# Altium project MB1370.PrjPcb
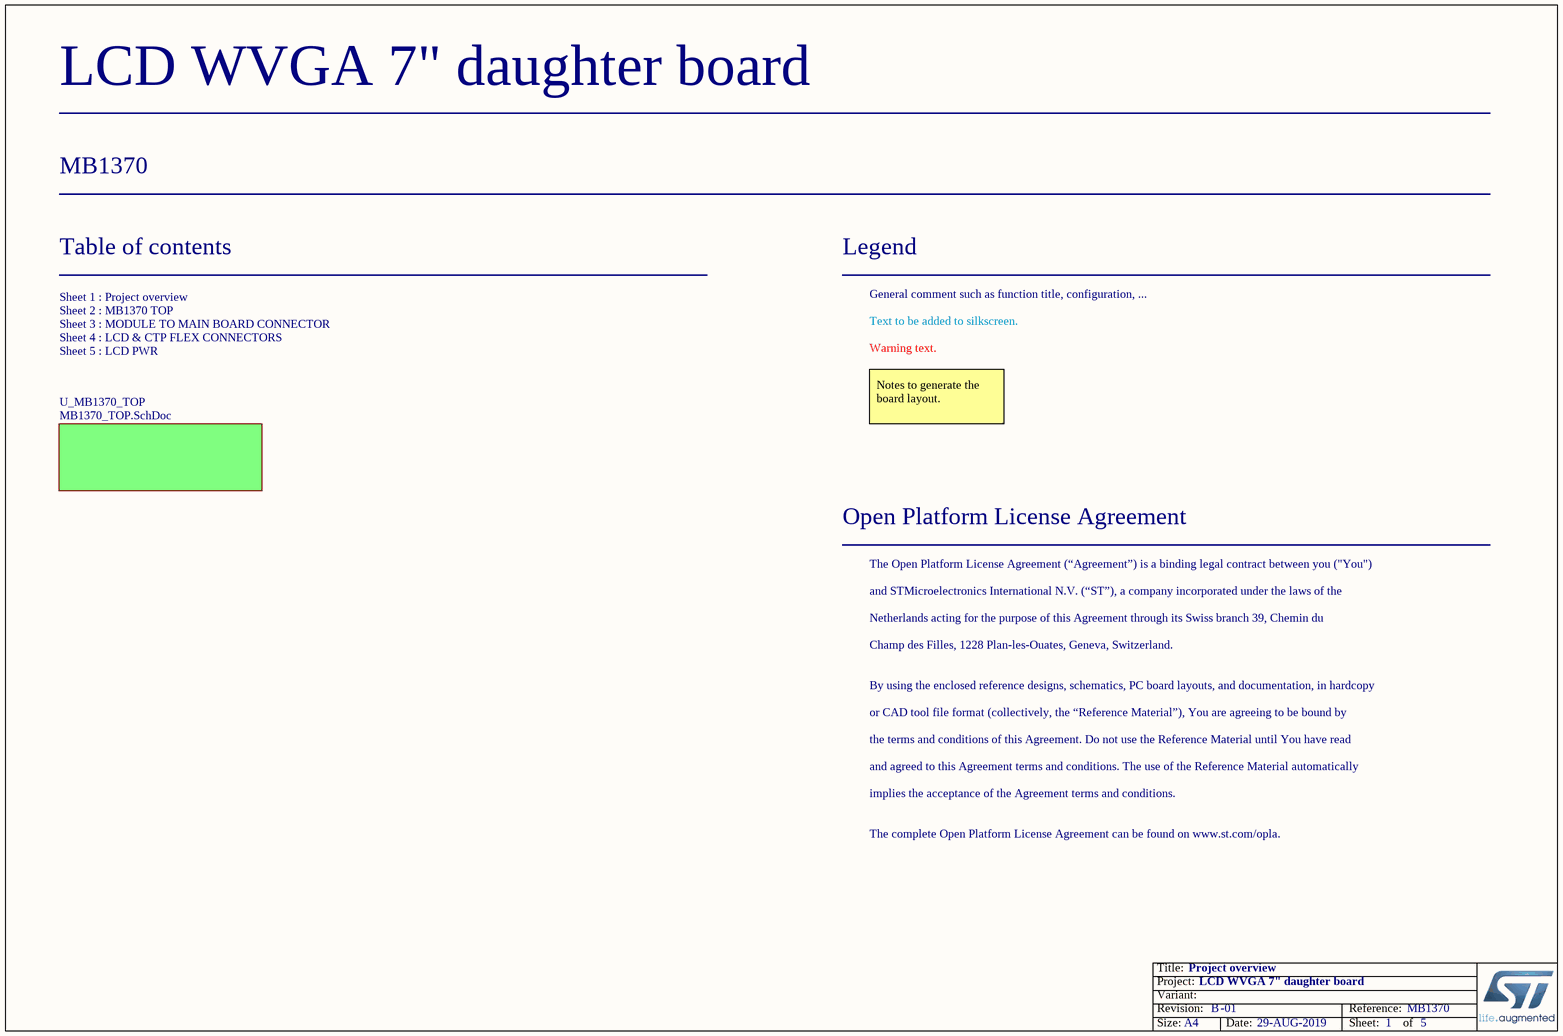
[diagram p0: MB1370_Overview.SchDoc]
Board_Assembly_Revision: 01; Board_Document_Date: 29-AUG-2019; Board_Name: LCD WVGA 7" daughter board; Board_PCB_Revision: B; Board_Reference: MB1370
5 sheets, 77 parts. Net scope: flat (ports and power ports of the same name join across sheets).
Board file: MB1370.PcbDoc
Sheets:
  MB1370_Overview.SchDoc
    U_MB1370_TOP = MB1370_TOP.SchDoc
      U_MODULE_TO_MAIN_BOARD_CONNECTOR = MODULE_TO_MAIN_BOARD_CONNECTOR.SchDoc
      U_LCD_CTP_FLEX_CONNECTORS = LCD_CTP_FLEX_CONNECTORS.SchDoc
      U_LCD_PWR = LCD_PWR.SchDoc

## Sheet MB1370_Overview.SchDoc: Project overview
size A4; Date: Not used; ApprovedBy: Not used; CheckedBy: Not used; Author: Not used; CompanyName: STMicroelectronics; DrawnBy: Not used; Engineer: Not used; Organization: Not used; Address1: Not used; Address2: Not used; Address3: Not used; Address4: Not used; DocumentNumber: Not used; Revision: Not used; SheetNumber: 1; SheetTotal: 5

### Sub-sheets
U_MB1370_TOP = MB1370_TOP.SchDoc: no entries

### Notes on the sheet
- Table of contents
- Legend
- General comment such as function title, configuration, ...
- Text to be added to silkscreen.
- Warning text.
- Sheet 1 : Project overview
  Sheet 2 : MB1370 TOP
  Sheet 3 : MODULE TO MAIN BOARD CONNECTOR
  Sheet 4 : LCD & CTP FLEX CONNECTORS
  Sheet 5 : LCD PWR
- Notes to generate the board layout.
- Open Platform License Agreement
- The Open Platform License Agreement (“Agreement”) is a binding legal contract between you ("You")
- and STMicroelectronics International N.V. (“ST”), a company incorporated under the laws of the
- Netherlands acting for the purpose of this Agreement through its Swiss branch 39, Chemin du
- Champ des Filles, 1228 Plan-les-Ouates, Geneva, Switzerland.
- By using the enclosed reference designs, schematics, PC board layouts, and documentation, in hardcopy
- or CAD tool file format (collectively, the “Reference Material”), You are agreeing to be bound by
- the terms and conditions of this Agreement. Do not use the Reference Material until You have read
- and agreed to this Agreement terms and conditions. The use of the Reference Material automatically
- implies the acceptance of the Agreement terms and conditions.
- The complete Open Platform License Agreement can be found on www.st.com/opla.

## Sheet MB1370_TOP.SchDoc: MB1370 TOP
size A4; Date: Not used; ApprovedBy: Not used; CheckedBy: Not used; Author: Not used; CompanyName: STMicroelectronics; DrawnBy: Not used; Engineer: Not used; Organization: Not used; Address1: Not used; Address2: Not used; Address3: Not used; Address4: Not used; DocumentNumber: Not used; Revision: Not used; SheetNumber: 2; SheetTotal: 5
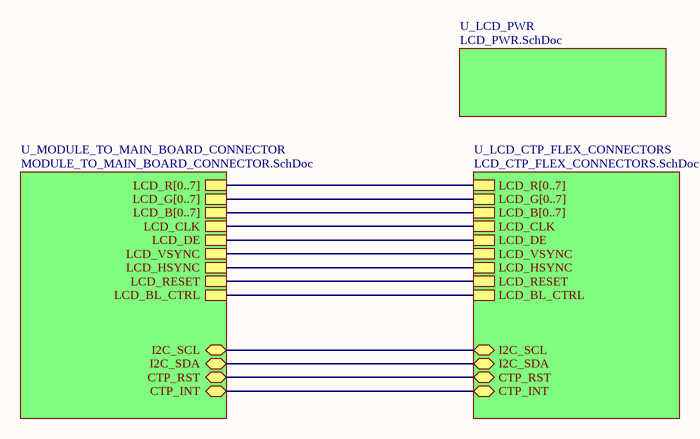
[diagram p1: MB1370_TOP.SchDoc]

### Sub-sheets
U_LCD_CTP_FLEX_CONNECTORS = LCD_CTP_FLEX_CONNECTORS.SchDoc: LCD_R[0..7], LCD_B[0..7], LCD_G[0..7], LCD_RESET, LCD_BL_CTRL, LCD_HSYNC, LCD_VSYNC, LCD_CLK, LCD_DE, I2C_SDA, I2C_SCL, CTP_RST, CTP_INT
U_LCD_PWR = LCD_PWR.SchDoc: no entries
U_MODULE_TO_MAIN_BOARD_CONNECTOR = MODULE_TO_MAIN_BOARD_CONNECTOR.SchDoc: LCD_R[0..7], LCD_B[0..7], LCD_G[0..7], LCD_HSYNC, LCD_VSYNC, LCD_CLK, LCD_DE, LCD_BL_CTRL, LCD_RESET, I2C_SCL, I2C_SDA, CTP_RST, CTP_INT

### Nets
(unnamed): sheet U_MODULE_TO_MAIN_BOARD_CONNECTOR/LCD_HSYNC, sheet U_LCD_CTP_FLEX_CONNECTORS/LCD_HSYNC
(unnamed): sheet U_MODULE_TO_MAIN_BOARD_CONNECTOR/LCD_VSYNC, sheet U_LCD_CTP_FLEX_CONNECTORS/LCD_VSYNC  [a separate net that carries the same name]
(unnamed): sheet U_MODULE_TO_MAIN_BOARD_CONNECTOR/LCD_CLK, sheet U_LCD_CTP_FLEX_CONNECTORS/LCD_CLK  [a separate net that carries the same name]
(unnamed): sheet U_MODULE_TO_MAIN_BOARD_CONNECTOR/LCD_DE, sheet U_LCD_CTP_FLEX_CONNECTORS/LCD_DE  [a separate net that carries the same name]
(unnamed): sheet U_MODULE_TO_MAIN_BOARD_CONNECTOR/LCD_BL_CTRL, sheet U_LCD_CTP_FLEX_CONNECTORS/LCD_BL_CTRL  [a separate net that carries the same name]
(unnamed): sheet U_MODULE_TO_MAIN_BOARD_CONNECTOR/LCD_RESET, sheet U_LCD_CTP_FLEX_CONNECTORS/LCD_RESET  [a separate net that carries the same name]
(unnamed): sheet U_MODULE_TO_MAIN_BOARD_CONNECTOR/I2C_SCL, sheet U_LCD_CTP_FLEX_CONNECTORS/I2C_SCL  [a separate net that carries the same name]
(unnamed): sheet U_MODULE_TO_MAIN_BOARD_CONNECTOR/I2C_SDA, sheet U_LCD_CTP_FLEX_CONNECTORS/I2C_SDA  [a separate net that carries the same name]
(unnamed): sheet U_MODULE_TO_MAIN_BOARD_CONNECTOR/CTP_RST, sheet U_LCD_CTP_FLEX_CONNECTORS/CTP_RST  [a separate net that carries the same name]
(unnamed): sheet U_MODULE_TO_MAIN_BOARD_CONNECTOR/CTP_INT, sheet U_LCD_CTP_FLEX_CONNECTORS/CTP_INT  [a separate net that carries the same name]

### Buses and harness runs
bus sheet U_LCD_CTP_FLEX_CONNECTORS/LCD_B[0..7] = sheet U_MODULE_TO_MAIN_BOARD_CONNECTOR/LCD_B[0..7]
bus sheet U_LCD_CTP_FLEX_CONNECTORS/LCD_G[0..7] = sheet U_MODULE_TO_MAIN_BOARD_CONNECTOR/LCD_G[0..7]
bus sheet U_LCD_CTP_FLEX_CONNECTORS/LCD_R[0..7] = sheet U_MODULE_TO_MAIN_BOARD_CONNECTOR/LCD_R[0..7]

## Sheet MODULE_TO_MAIN_BOARD_CONNECTOR.SchDoc: MODULE TO MAIN BOARD CONNECTOR
size A4; Date: Not used; ApprovedBy: Not used; CheckedBy: Not used; Author: Not used; CompanyName: STMicroelectronics; DrawnBy: Not used; Engineer: Not used; Organization: Not used; Address1: Not used; Address2: Not used; Address3: Not used; Address4: Not used; DocumentNumber: Not used; Revision: Not used; SheetNumber: 3; SheetTotal: 5
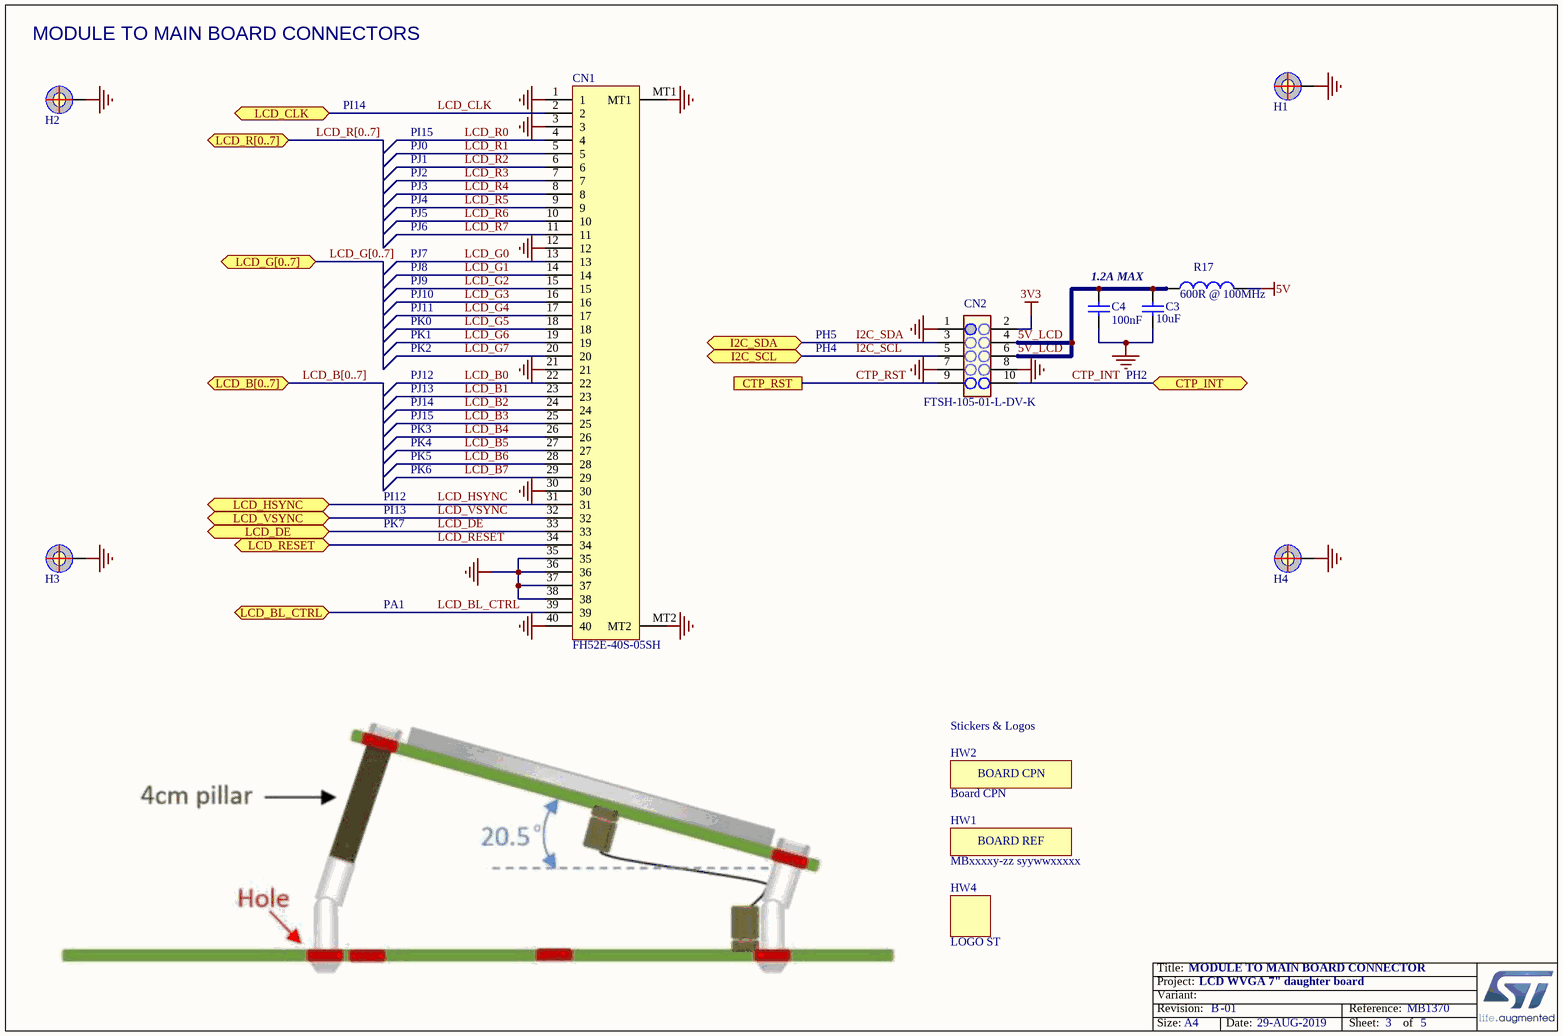
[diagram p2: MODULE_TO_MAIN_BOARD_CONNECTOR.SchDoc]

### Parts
C3  value 10uF  [C0805]  (hidden comment: Capacitor)
C4  value 100nF  [C0402]  (hidden comment: Capacitor)
CN1  value FH52E-40S-05SH  [CON_HRS_FH52E-40S-05SH]  (hidden comment: FH52E-40S-0.5SH)
CN2  value FTSH-105-01-L-DV-K  [CON_SAMTEC_FTSH-105-01-L-DV-K]  (hidden comment: Header 5x2 Generic)
H1  POSITION HOLE  [PTH_M1261-3005-N_3P5X6_M3_H14]  (value not drawn)  (no BOM)
H2  POSITION HOLE  [PTH_M1261-3005-N_3P5X6_M3_H14]  (value not drawn)  (no BOM)
H3  POSITION HOLE  [PTH_M1261-3005-N_3P5X6_M3_H14]  (value not drawn)  (no BOM)
H4  POSITION HOLE  [PTH_M1261-3005-N_3P5X6_M3_H14]  (value not drawn)  (no BOM)
HW1  value MBxxxxy-zz syywwxxxxx  [STICKER_25X9]  (hidden comment: STICKER_BOARD_REF)  (no BOM)
HW2  value Board CPN  [STICKER_25X9]  (hidden comment: STICKER_BOARD_CPN)  (no BOM)
HW4  value LOGO ST  [LOGO_ST]  (hidden comment: Logo)  (no BOM)
R17  value 600R @ 100MHz  [IND_0603_H0P8]  (hidden comment: Inductor)

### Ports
CTP_INT, CTP_RST, I2C_SCL, I2C_SDA, LCD_B[0..7], LCD_BL_CTRL, LCD_CLK, LCD_DE, LCD_G[0..7], LCD_HSYNC, LCD_R[0..7], LCD_RESET, LCD_VSYNC

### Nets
3V3: CN2.2
5V: R17.2
GND: C3.1 C4.2 CN1.1 CN1.3 CN1.12 CN1.21 CN1.30 CN1.35 CN1.36 CN1.37 CN1.38 CN1.40 CN1.MT1 CN1.MT2 CN2.1 CN2.7 CN2.8 H1.1 H2.1 H3.1 H4.1
5V_LCD: C3.2 C4.1 CN2.4 CN2.6 R17.1
CTP_INT: CN2.10 ; port CTP_INT
CTP_RST: CN2.9 ; port CTP_RST
I2C_SCL: CN2.5 ; port I2C_SCL
I2C_SDA: CN2.3 ; port I2C_SDA
LCD_B0: CN1.22
LCD_B1: CN1.23
LCD_B2: CN1.24
LCD_B3: CN1.25
LCD_B4: CN1.26
LCD_B5: CN1.27
LCD_B6: CN1.28
LCD_B7: CN1.29
LCD_BL_CTRL: CN1.39 ; port LCD_BL_CTRL
LCD_CLK: CN1.2 ; port LCD_CLK
LCD_DE: CN1.33 ; port LCD_DE
LCD_G0: CN1.13
LCD_G1: CN1.14
LCD_G2: CN1.15
LCD_G3: CN1.16
LCD_G4: CN1.17
LCD_G5: CN1.18
LCD_G6: CN1.19
LCD_G7: CN1.20
LCD_HSYNC: CN1.31 ; port LCD_HSYNC
LCD_R0: CN1.4
LCD_R1: CN1.5
LCD_R2: CN1.6
LCD_R3: CN1.7
LCD_R4: CN1.8
LCD_R5: CN1.9
LCD_R6: CN1.10
LCD_R7: CN1.11
LCD_RESET: CN1.34 ; port LCD_RESET
LCD_VSYNC: CN1.32 ; port LCD_VSYNC

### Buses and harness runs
bus LCD_B[0..7] = port LCD_B[0..7]
bus LCD_G[0..7] = port LCD_G[0..7]
bus LCD_R[0..7] = port LCD_R[0..7]

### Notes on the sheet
- MODULE TO MAIN BOARD CONNECTORS
- PI14
- PI15
- PJ0
- PJ1
- PJ2
- PJ3
- PJ4
- PJ5
- PJ6
- PJ7
- PJ8
- PJ9
- PJ10
- PJ11
- 1.2A MAX
- PK0
- PK1
- PK2
- PJ12
- PH5
- PH4
- PH2
- PJ13
- PJ14
- PJ15
- PK3
- PK4
- PI12
- PI13
- PK5
- PK6
- PK7
- PA1
- (near HW2) Stickers & Logos

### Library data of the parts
C3 = MCD-00014: Capacitor, MLCC, 10uF, 25V, X5R, 10%, 0805, T=0,85mm; Manufacturer_Part_Number: CC0805KRX5R8BB106; Manufacturer: YAGEO; Provided_By: SUBCO; ECCN_US: EAR99; ECCN_EU: NEC
C4 = MCD-00006: Capacitor, MLCC, 100nF, 16V, X7R, 10%, 0402, T=0.5mm; Manufacturer_Part_Number: CC0402KRX7R7BB104; Manufacturer: YAGEO; Alternate_Manufacturer_Part_Number: GCM155R71C104KA55D; Alternate_Manufacturer: MURATA; Provided_By: SUBCO; ECCN_US: EAR99; ECCN_EU: NEC
CN1 = MCD-01992: FFC et FPC connector 0.5MM 40P LNG MTL FITNG SMT VERT MNT; Manufacturer: HIROSE; ECCN_US: EAR99; ECCN_EU: NEC; Provided_By: SUBCO
CN2 = MCD-00610: Surface mount, vertical male connector. Double row of 5 pins, 1.27mm pitch, 3.05mm lead. Mates with FFSD connector; Manufacturer: SAMTEC; Alternate_Manufacturer_Part_Number: P127B-2x05MGF-079-1A; Alternate_Manufacturer: JIUBABA; Provided_By: SUBCO
H1-H4 = MCD-00035: POSITION HOLE C6D3R5; Part_Type: Mechanical
HW1 = MCD-00235: Sticker to mention board reference + serial number; Part_Type: Mechanical; Provided_By: SUBCO
HW2 = MCD-00547: Sticker to mention board CPN code; Part_Type: Mechanical; Provided_By: SUBCO
HW4 = MCD-00625: STMicroelectronics logo footprint for PCB; Part_Type: Mechanical
R17 = MCD-00593: Ferrite bead, 600R @ 100MHz,  1.3A, 150mOhm, 0603; Manufacturer_Part_Number: BLM18KG601SN1D; Manufacturer: MURATA; ECCN_US: EAR99; ECCN_EU: NEC; Provided_By: SUBCO

## Sheet LCD_CTP_FLEX_CONNECTORS.SchDoc: LCD & CTP FLEX CONNECTORS
size A4; Date: Not used; ApprovedBy: Not used; CheckedBy: Not used; Author: Not used; CompanyName: STMicroelectronics; DrawnBy: Not used; Engineer: Not used; Organization: Not used; Address1: Not used; Address2: Not used; Address3: Not used; Address4: Not used; DocumentNumber: Not used; Revision: Not used; SheetNumber: 4; SheetTotal: 5
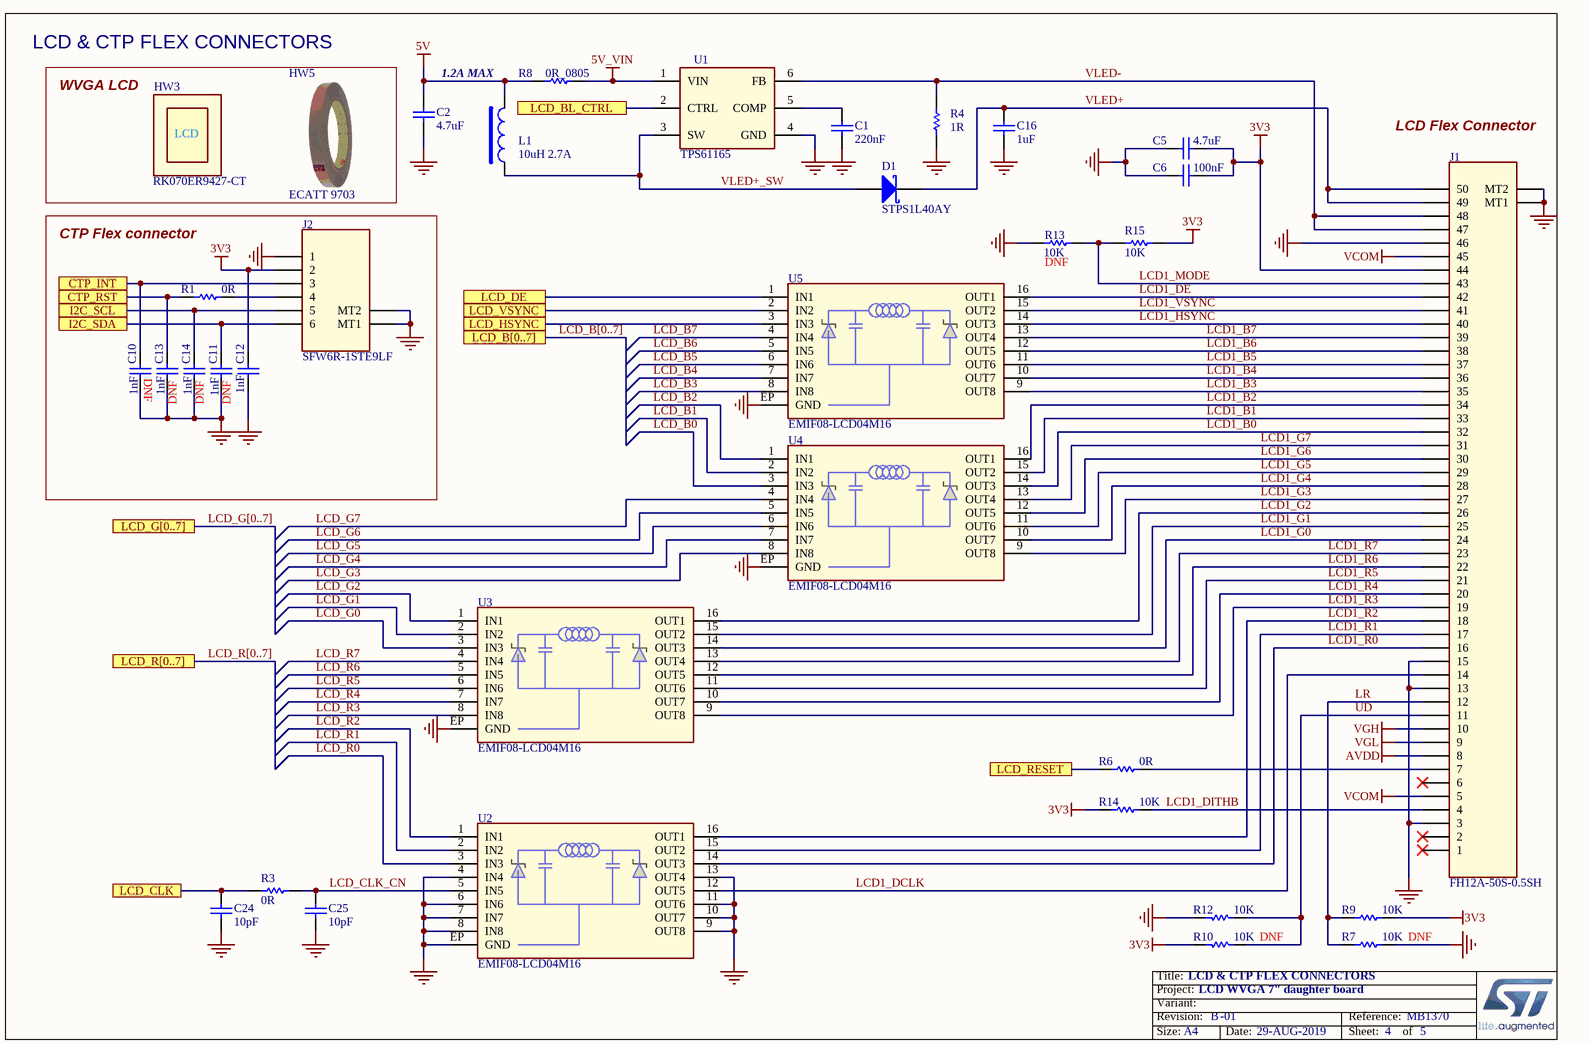
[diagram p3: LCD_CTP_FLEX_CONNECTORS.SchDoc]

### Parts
C1  value 220nF  [C0402]  (hidden comment: Capacitor)
C2  value 4.7uF  [C0805]  (hidden comment: Capacitor)
C5  value 4.7uF  [C0603]  (hidden comment: Capacitor)
C6  value 100nF  [C0402]  (hidden comment: Capacitor)
C10  value 1nF  [C0402]  (hidden comment: Capacitor)
C11  value 1nF  [C0402]  (hidden comment: Capacitor)
C12  value 1nF  [C0402]  (hidden comment: Capacitor)
C13  value 1nF  [C0402]  (hidden comment: Capacitor)
C14  value 1nF  [C0402]  (hidden comment: Capacitor)
C16  value 1uF  [C1206_H1P15]  (hidden comment: Capacitor)
C24  value 10pF  [C0402]  (hidden comment: Capacitor)
C25  value 10pF  [C0402]  (hidden comment: Capacitor)
D1  value STPS1L40AY  [DIO_SMA_1A_2K]  (hidden comment: SCHOTTKY_1A_2K)
HW3  value RK070ER9427-CT  [LCD_DRAWING_ROCKTEK_RK070ER9427-CT]  (hidden comment: LCD_RK070ER9427L)
HW5  value ECATT 9703  (hidden comment: ECATT_9703)  (mechanical)
J1  value FH12A-50S-0.5SH  [CON_HRS_FH12A-50S-05SH]  (hidden comment: CONN_FH12S-50S-05SH)
J2  value SFW6R-1STE9LF  [CON_FCI_SFW6R-1STE9LF]  (hidden comment: CONN_FH12S-6S-05SH)
L1  value 10uH 2.7A  [IND_TDK_CLF7045T-100M-D]  (hidden comment: INDUCTOR_POWER)
R1  value 0R  [R0603]  (hidden comment: Resistor)
R3  value 0R  [R0402]  (hidden comment: Resistor)
R4  value 1R  [R0805]  (hidden comment: Resistor)
R6  value 0R  [R0603]  (hidden comment: Resistor)
R7  value 10K  [R0402]  (hidden comment: Resistor)
R8  value 0R_0805  [R0805]  (hidden comment: Resistor)
R9  value 10K  [R0402]  (hidden comment: Resistor)
R10  value 10K  [R0402]  (hidden comment: Resistor)
R12  value 10K  [R0402]  (hidden comment: Resistor)
R13  value 10K  [R0402]  (hidden comment: Resistor)
R14  value 10K  [R0402]  (hidden comment: Resistor)
R15  value 10K  [R0402]  (hidden comment: Resistor)
U1  TPS61165  [MOS_SOT23-6L]
U2  value EMIF08-LCD04M16  [ESD_UQFN16L-EPAD_3P3X1P35_P040]  (hidden comment: FIL_EMIF_ESD_8L)
U3  value EMIF08-LCD04M16  [ESD_UQFN16L-EPAD_3P3X1P35_P040]  (hidden comment: FIL_EMIF_ESD_8L)
U4  value EMIF08-LCD04M16  [ESD_UQFN16L-EPAD_3P3X1P35_P040]  (hidden comment: FIL_EMIF_ESD_8L)
U5  value EMIF08-LCD04M16  [ESD_UQFN16L-EPAD_3P3X1P35_P040]  (hidden comment: FIL_EMIF_ESD_8L)

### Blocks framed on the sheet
WVGA LCD: HW3 HW5
CTP Flex connector: C10-C14 J2 R1

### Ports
CTP_INT, CTP_RST, I2C_SCL, I2C_SDA, LCD_B[0..7], LCD_BL_CTRL, LCD_CLK, LCD_DE, LCD_G[0..7], LCD_HSYNC, LCD_R[0..7], LCD_RESET, LCD_VSYNC

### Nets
3V3: C5.2 C6.2 C12.2 J1.44 J2.2 R9.2 R10.2 R14.1 R15.2
5V: C2.2 L1.2 R8.1
5V_VIN: R8.2 U1.1(VIN)
AVDD: J1.8
GND: C1.1 C2.1 C5.1 C6.1 C10.1 C11.1 C12.1 C13.1 C14.1 C16.1 C24.1 C25.1 J1.3 J1.13 J1.15 J1.46 J1.MT1 J1.MT2 J2.1 J2.MT1 J2.MT2 R4.1 R7.2 R12.2 R13.1 U1.4(GND) U2.4(IN4) U2.6(IN6) U2.7(IN7) U2.8(IN8) U2.9(OUT8) U2.10(OUT7) U2.11(OUT6) U2.13(OUT4) U2.EP(GND) U3.EP(GND) U4.EP(GND) U5.EP(GND)
VCOM: J1.5 J1.45
VGH: J1.10
VGL: J1.9
CTP_INT: C10.2 J2.3 ; port CTP_INT
CTP_RST: C13.2 R1.1 ; port CTP_RST
I2C_SCL: C14.2 J2.5 ; port I2C_SCL
I2C_SDA: C11.2 J2.6 ; port I2C_SDA
LCD1_B0: J1.32 U4.14(OUT3)
LCD1_B1: J1.33 U4.15(OUT2)
LCD1_B2: J1.34 U4.16(OUT1)
LCD1_B3: J1.35 U5.9(OUT8)
LCD1_B4: J1.36 U5.10(OUT7)
LCD1_B5: J1.37 U5.11(OUT6)
LCD1_B6: J1.38 U5.12(OUT5)
LCD1_B7: J1.39 U5.13(OUT4)
LCD1_DCLK: J1.14 U2.12(OUT5)
LCD1_DE: J1.42 U5.16(OUT1)
LCD1_DITHB: J1.4 R14.2
LCD1_G0: J1.24 U3.14(OUT3)
LCD1_G1: J1.25 U3.15(OUT2)
LCD1_G2: J1.26 U3.16(OUT1)
LCD1_G3: J1.27 U4.9(OUT8)
LCD1_G4: J1.28 U4.10(OUT7)
LCD1_G5: J1.29 U4.11(OUT6)
LCD1_G6: J1.30 U4.12(OUT5)
LCD1_G7: J1.31 U4.13(OUT4)
LCD1_HSYNC: J1.40 U5.14(OUT3)
LCD1_MODE: J1.43 R13.2 R15.1
LCD1_R0: J1.16 U2.14(OUT3)
LCD1_R1: J1.17 U2.15(OUT2)
LCD1_R2: J1.18 U2.16(OUT1)
LCD1_R3: J1.19 U3.9(OUT8)
LCD1_R4: J1.20 U3.10(OUT7)
LCD1_R5: J1.21 U3.11(OUT6)
LCD1_R6: J1.22 U3.12(OUT5)
LCD1_R7: J1.23 U3.13(OUT4)
LCD1_VSYNC: J1.41 U5.15(OUT2)
LCD_B0: U4.3(IN3)
LCD_B1: U4.2(IN2)
LCD_B2: U4.1(IN1)
LCD_B3: U5.8(IN8)
LCD_B4: U5.7(IN7)
LCD_B5: U5.6(IN6)
LCD_B6: U5.5(IN5)
LCD_B7: U5.4(IN4)
LCD_BL_CTRL: U1.2(CTRL) ; port LCD_BL_CTRL
LCD_CLK: C24.2 R3.1 ; port LCD_CLK
LCD_CLK_CN: C25.2 R3.2 U2.5(IN5)
LCD_DE: U5.1(IN1) ; port LCD_DE
LCD_G0: U3.3(IN3)
LCD_G1: U3.2(IN2)
LCD_G2: U3.1(IN1)
LCD_G3: U4.8(IN8)
LCD_G4: U4.7(IN7)
LCD_G5: U4.6(IN6)
LCD_G6: U4.5(IN5)
LCD_G7: U4.4(IN4)
LCD_HSYNC: U5.3(IN3) ; port LCD_HSYNC
LCD_R0: U2.3(IN3)
LCD_R1: U2.2(IN2)
LCD_R2: U2.1(IN1)
LCD_R3: U3.8(IN8)
LCD_R4: U3.7(IN7)
LCD_R5: U3.6(IN6)
LCD_R6: U3.5(IN5)
LCD_R7: U3.4(IN4)
LCD_RESET: R6.1 ; port LCD_RESET
LCD_VSYNC: U5.2(IN2) ; port LCD_VSYNC
LR: J1.12 R7.1 R9.1
UD: J1.11 R10.1 R12.1
VLED+: C16.2 D1.2(K) J1.49 J1.50
VLED+_SW: D1.1(A) L1.1 U1.3(SW)
VLED-: J1.47 J1.48 R4.2 U1.6(FB)
NetC1_2: C1.2 U1.5(COMP)
NetJ1_7: J1.7 R6.2
NetJ2_4: J2.4 R1.2

Not connected (* = marked no-connect by the designer): J1 1* 2* 6*

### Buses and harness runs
bus LCD_B[0..7] = port LCD_B[0..7]
bus LCD_G[0..7] = port LCD_G[0..7]
bus LCD_R[0..7] = port LCD_R[0..7]

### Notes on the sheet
- LCD & CTP FLEX CONNECTORS
- 1.2A MAX
- LCD Flex Connector
- (near R13) DNF
- (near C10) DNF
- DNF

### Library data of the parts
C1 = MCD-00602: Capacitor, MLCC, 220nF, 16V, 0402, X7R, 10%, T=0,5mm; Manufacturer_Part_Number: GRM155R71C223KA01J; Manufacturer: MURATA; Provided_By: SUBCO; ECCN_US: EAR99; ECCN_EU: NEC
C2 = MCD-01974: Capacitor, MLCC, 4.7uF, 16V, 0805, X5R, 10%, T=1,25mm; Manufacturer_Part_Number: EMK212ABJ475KG-T; Manufacturer: TAIYO YUDEN; Alternate_Manufacturer_Part_Number: C0805C475K4PACTU; Alternate_Manufacturer: KEMET; Order_Code_RS: 691-1189; ECCN_US: EAR99; ECCN_EU: NEC; Provided_By: SUBCO
C5 = MCD-00009: Capacitor, MLCC, 4.7uF, 16V, X5R, 10%, 0603, T=0.8mm; Manufacturer_Part_Number: CC0603KRX5R7BB475; Manufacturer: YAGEO; Provided_By: SUBCO; ECCN_US: EAR99; ECCN_EU: NEC
C6 = MCD-00006: Capacitor, MLCC, 100nF, 16V, X7R, 10%, 0402, T=0.5mm; Manufacturer_Part_Number: CC0402KRX7R7BB104; Manufacturer: YAGEO; Alternate_Manufacturer_Part_Number: GCM155R71C104KA55D; Alternate_Manufacturer: MURATA; ECCN_US: EAR99; ECCN_EU: NEC; Provided_By: SUBCO
C10-C14 = MCD-00198: Capacitor, MLCC, 1nF, 16V, X7R, 10%, 0402, T=0.5mm; Manufacturer_Part_Number: CC0402KRX7R7BB102; Manufacturer: YAGEO; Provided_By: SUBCO; ECCN_US: EAR99; ECCN_EU: NEC
C16 = MCD-01997: Capacitor, MLCC, 1uF, 50V, 1206, X7R, 10%, T=1mm; Manufacturer_Part_Number: C1206C105K5RACTU; Manufacturer: KEMET; Provided_By: SUBCO; ECCN_US: EAR99; ECCN_EU: NEC
C24 C25 = MCD-00015: Capacitor, MLCC, 10pF, 50V, NPO, 5%, 0402, T=0,5mm; Manufacturer_Part_Number: CC0402JRNPO9BN100; Manufacturer: YAGEO; ECCN_US: EAR99; ECCN_EU: NEC; Provided_By: SUBCO
D1 = MCD-00606: Low Drop power Schottky rectifier(1A, 40V, 0.37 V); Manufacturer: STMICROELECTRONICS; Part_Type: Diode; BMS_Part_Number: 9151017; Provided_By: SUBCO with ST control; ECCN_US: EAR99; ECCN_EU: NEC
HW3 = MCD-00604: Display (TFT LCD) - 7-inch LCD Module 800x480 (RGB 24-bit) with integrated capacitive touch panel; Manufacturer: ROCKTEK; Provided_By: SUBCO
HW5 = MCD-01990: Electrically Conductive Adhesive Transfer Tape; Part_Type: Mechanical; Manufacturer_Part_Number: 9703; Manufacturer: 3M; ECCN_US: EAR99; ECCN_EU: NEC; Provided_By: SUBCO
J1 = MCD-01042: 50-pin 05mm Pitch connector for FPC/FFC top contact version; Manufacturer: HIROSE; Provided_By: SUBCO
J2 = MCD-01363: 6-pin 1mm Pitch SMT connector for FPC/FFC lower contact type; Manufacturer: FCI; Provided_By: SUBCO
L1 = MCD-00615: Magnetic shield type wound inductor for power circuits 10uH 38mOhms 2.7A 20%; Manufacturer_Part_Number: CLF7045T-100M-D; Manufacturer: TDK; Provided_By: SUBCO
R1 R6 = MCD-00056: Resistor,0R,0603,5%,1/10W; Manufacturer_Part_Number: RC0603JR-070RL; Manufacturer: YAGEO; Provided_By: SUBCO; ECCN_US: EAR99; ECCN_EU: NEC
R3 = MCD-00052: Resistor,0R,0402,5%,1/16W; Manufacturer_Part_Number: RC0402JR-070RL; Manufacturer: YAGEO; ECCN_US: EAR99; ECCN_EU: NEC; Provided_By: SUBCO
R4 = MCD-00323: Resistor, 1R, 0805, 1%, 1/8W; Manufacturer_Part_Number: RC0805FR-071RL; Manufacturer: YAGEO; Provided_By: SUBCO; ECCN_US: EAR99; ECCN_EU: NEC
R7 R9 R10 R12-R15 = MCD-00053: Resistor,10K,0402,1%,1/16W; Manufacturer_Part_Number: RC0402FR-0710KL; Manufacturer: YAGEO; Provided_By: SUBCO; ECCN_US: EAR99; ECCN_EU: NEC
R8 = MCD-00179: Resistor,0R,0805,5%; Manufacturer_Part_Number: RC0805JR-070RL; Manufacturer: YAGEO; Provided_By: SUBCO; ECCN_US: EAR99; ECCN_EU: NEC
U1 = MCD-00601: High-Brightness White LED Driver in SOT-23 Package; Manufacturer: TEXAS INSTRUMENTS; Part_Type: IC; Provided_By: SUBCO; ECCN_US: EAR99
U2-U5 = MCD-00599: 8-line L-C EMI filter and ESD protection for LCD application; Part_Type: Diode; Manufacturer: STMICROELECTRONICS; BMS_Part_Number: 9179004; Provided_By: SUBCO with ST control; ECCN_US: EAR99; ECCN_EU: NEC

## Sheet LCD_PWR.SchDoc: LCD POWER
size A4; Date: Not used; ApprovedBy: Not used; CheckedBy: Not used; Author: Not used; CompanyName: STMicroelectronics; DrawnBy: Not used; Engineer: Not used; Organization: Not used; Address1: Not used; Address2: Not used; Address3: Not used; Address4: Not used; DocumentNumber: Not used; Revision: Not used; SheetNumber: 5; SheetTotal: 5
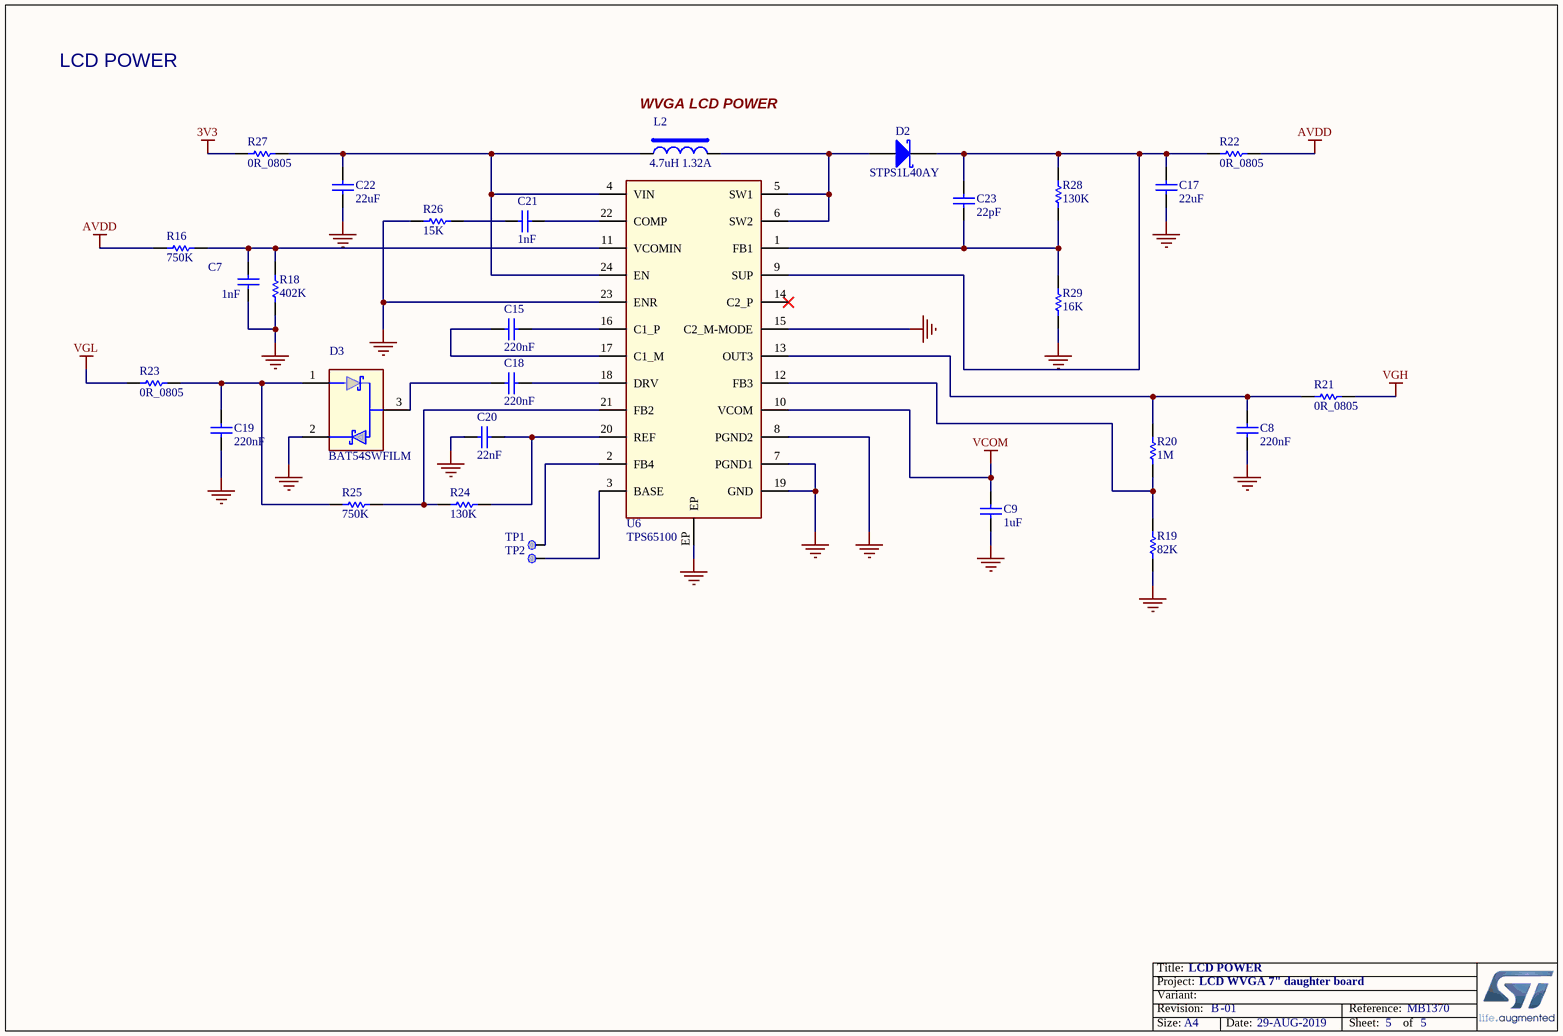
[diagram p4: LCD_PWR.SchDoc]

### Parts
C7  value 1nF  [C0402]  (hidden comment: Capacitor)
C8  value 220nF  [C0402]  (hidden comment: Capacitor)
C9  value 1uF  [C1206_H1P15]  (hidden comment: Capacitor)
C15  value 220nF  [C0402]  (hidden comment: Capacitor)
C17  value 22uF  [C1210]  (hidden comment: Capacitor)
C18  value 220nF  [C0402]  (hidden comment: Capacitor)
C19  value 220nF  [C0402]  (hidden comment: Capacitor)
C20  value 22nF  [C0402]  (hidden comment: Capacitor)
C21  value 1nF  [C0402]  (hidden comment: Capacitor)
C22  value 22uF  [C1210]  (hidden comment: Capacitor)
C23  value 22pF  [C0402]  (hidden comment: Capacitor)
D2  value STPS1L40AY  [DIO_SMA_1A_2K]  (hidden comment: SCHOTTKY_1A_2K)
D3  value BAT54SWFILM  [DIO_SOT323]  (hidden comment: DIODE_3P_DUAL_SERIES)
L2  value 4.7uH 1.32A  [IND_TDK_VLS4012ET-4R7M]  (hidden comment: INDUCTOR_POWER)
R16  value 750K  [R0402]  (hidden comment: Resistor)
R18  value 402K  [R0402]  (hidden comment: Resistor)
R19  value 82K  [R0402]  (hidden comment: Resistor)
R20  value 1M  [R0402]  (hidden comment: Resistor)
R21  value 0R_0805  [R0805]  (hidden comment: Resistor)
R22  value 0R_0805  [R0805]  (hidden comment: Resistor)
R23  value 0R_0805  [R0805]  (hidden comment: Resistor)
R24  value 130K  [R0402]  (hidden comment: Resistor)
R25  value 750K  [R0402]  (hidden comment: Resistor)
R26  value 15K  [R0402]  (hidden comment: Resistor)
R27  value 0R_0805  [R0805]  (hidden comment: Resistor)
R28  value 130K  [R0402]  (hidden comment: Resistor)
R29  value 16K  [R0402]  (hidden comment: Resistor)
TP1  Test Point  [TP_SMD_1MM]  (value not drawn)  (no BOM)
TP2  Test Point  [TP_SMD_1MM]  (value not drawn)  (no BOM)
U6  TPS65100  [ICC_HTSSOP24-EPAD_7P8X4P4_P065]

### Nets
3V3: R27.1
AVDD: R16.1 R22.2
GND: C7.1 C8.1 C9.1 C17.1 C19.1 C20.1 C22.1 D3.2 R18.1 R19.1 R26.1 R29.1 U6.7(PGND1) U6.8(PGND2) U6.15(C2_M-MODE) U6.19(GND) U6.23(ENR) U6.EP
VCOM: C9.2 U6.10(VCOM)
VGH: R21.2
VGL: R23.1
NetC7_2: C7.2 R16.2 R18.2 U6.11(VCOMIN)
NetC8_2: C8.2 R20.2 R21.1 U6.13(OUT3)
NetC15_1: C15.1 U6.16(C1_P)
NetC15_2: C15.2 U6.17(C1_M)
NetC17_2: C17.2 C23.2 D2.2(K) R22.1 R28.2 U6.9(SUP)
NetC18_1: C18.1 U6.18(DRV)
NetC18_2: C18.2 D3.3
NetC19_2: C19.2 D3.1 R23.2 R25.1
NetC20_2: C20.2 R24.2 U6.20(REF)
NetC21_1: C21.1 U6.22(COMP)
NetC21_2: C21.2 R26.2
NetC22_2: C22.2 L2.1 R27.2 U6.4(VIN) U6.24(EN)
NetC23_1: C23.1 R28.1 R29.2 U6.1(FB1)
NetD2_1: D2.1(A) L2.2 U6.5(SW1) U6.6(SW2)
NetR19_2: R19.2 R20.1 U6.12(FB3)
NetR24_1: R24.1 R25.2 U6.21(FB2)
NetTP1_1: TP1.1 U6.2(FB4)
NetTP2_1: TP2.1 U6.3(BASE)

Not connected (* = marked no-connect by the designer): U6 14(C2_P)*

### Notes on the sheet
- LCD POWER
- (near L2) WVGA LCD POWER

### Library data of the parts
C7 C21 = MCD-00198: as C10 on sheet LCD_CTP_FLEX_CONNECTORS
C8 C15 C18 C19 = MCD-00602: as C1 on sheet LCD_CTP_FLEX_CONNECTORS
C9 = MCD-01997: as C16 on sheet LCD_CTP_FLEX_CONNECTORS
C17 C22 = MCD-00614: Capacitor, MLCC, 22uF, 16V, 1210, X7R, 20%, T=2,5mm, ESR 2mohm@410KHz; Manufacturer_Part_Number: GCM32ER71C226ME19; Manufacturer: MURATA; Provided_By: SUBCO; ECCN_US: EAR99; ECCN_EU: NEC
C20 = MCD-00202: Capacitor, MLCC, 22nF, 16V, X7R, 10%, 0402, T=0.5mm; Manufacturer_Part_Number: CC0402KRX7R7BB223; Manufacturer: YAGEO; Provided_By: SUBCO; ECCN_US: EAR99; ECCN_EU: NEC
C23 = MCD-01995: Capacitor, MLCC, 22pF, 50V, C0G, 5%, 0402, T=0,5mm; Manufacturer_Part_Number: C1005NP01H220J050BA; Manufacturer: TDK; Provided_By: SUBCO; ECCN_US: EAR99; ECCN_EU: NEC
D2 = MCD-00606: as D1 on sheet LCD_CTP_FLEX_CONNECTORS
D3 = MCD-00608: Dual surface mount small signal schotky diode in series; Manufacturer: STMICROELECTRONICS; Provided_By: SUBCO with ST control; ECCN_US: EAR99; ECCN_EU: NEC
L2 = MCD-01996: Surface mount Wound Magnetically shielded Power inductor. 4.7uH +/-20%; DCres:95mohm; 1.32A(-30% from initial value); 1.57A(+40°C temperature rise); Manufacturer_Part_Number: NRS4012T4R7MDGJ; Manufacturer: TAIYO YUDEN; Provided_By: SUBCO; ECCN_US: EAR99; ECCN_EU: NEC
R16 R25 = MCD-00523: Resistor,750K,0402,1%,1/16W; Manufacturer_Part_Number: RC0402FR-07750KL; Manufacturer: YAGEO; Provided_By: SUBCO; ECCN_US: EAR99; ECCN_EU: NEC
R18 = MCD-00607: Resistor,402K,0402,1%,1/16W; Manufacturer_Part_Number: RC0402FR-07402KL; Manufacturer: YAGEO; Provided_By: SUBCO; ECCN_US: EAR99; ECCN_EU: NEC
R19 = MCD-00531: Resistor,82K,0402,1%,1/16W; Manufacturer_Part_Number: RC0402FR-0782KL; Manufacturer: YAGEO; Provided_By: SUBCO; ECCN_US: EAR99; ECCN_EU: NEC
R20 = MCD-00182: Resistor,1M,0402,1%,1/16W; Manufacturer_Part_Number: RC0402FR-071ML; Manufacturer: YAGEO; Provided_By: SUBCO; ECCN_US: EAR99; ECCN_EU: NEC
R21-R23 R27 = MCD-00179: as R8 on sheet LCD_CTP_FLEX_CONNECTORS
R24 R28 = MCD-00385: Resistor,130K,0402,1%,1/16W; Manufacturer_Part_Number: RC0402FR-07130KL; Manufacturer: YAGEO; Provided_By: SUBCO; ECCN_US: EAR99; ECCN_EU: NEC
R26 = MCD-00285: Resistor,15K,0402,5%,1/16W; Manufacturer_Part_Number: RC0402JR-0715KL; Manufacturer: YAGEO; Provided_By: SUBCO; ECCN_US: EAR99; ECCN_EU: NEC
R29 = MCD-00403: Resistor,16K,0402,1%,1/16W; Manufacturer_Part_Number: RC0402FR-0716KL; Manufacturer: YAGEO; Provided_By: SUBCO; ECCN_US: EAR99; ECCN_EU: NEC
TP1 TP2 = MCD-00074: Test Point 1mm; Part_Type: Mechanical
U6 = MCD-00613: Triple-Output LCD Supply With Linear Regulator and VCOM Buffer; Part_Type: IC; Manufacturer_Part_Number: TPS65100PWP; Manufacturer: TEXAS INSTRUMENTS; Provided_By: SUBCO; ECCN_US: EAR99

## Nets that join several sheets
3V3: MODULE_TO_MAIN_BOARD_CONNECTOR (CN2.2), LCD_CTP_FLEX_CONNECTORS (9 pins), LCD_PWR (R27.1)
5V: MODULE_TO_MAIN_BOARD_CONNECTOR (R17.2), LCD_CTP_FLEX_CONNECTORS (C2.2 L1.2 R8.1)
AVDD: LCD_CTP_FLEX_CONNECTORS (J1.8), LCD_PWR (R16.1 R22.2)
GND: MODULE_TO_MAIN_BOARD_CONNECTOR (21 pins), LCD_CTP_FLEX_CONNECTORS (38 pins), LCD_PWR (18 pins)
VCOM: LCD_CTP_FLEX_CONNECTORS (J1.5 J1.45), LCD_PWR (C9.2 U6.10)
VGH: LCD_CTP_FLEX_CONNECTORS (J1.10), LCD_PWR (R21.2)
VGL: LCD_CTP_FLEX_CONNECTORS (J1.9), LCD_PWR (R23.1)
CTP_INT: MODULE_TO_MAIN_BOARD_CONNECTOR (CN2.10), LCD_CTP_FLEX_CONNECTORS (C10.2 J2.3)
CTP_RST: MODULE_TO_MAIN_BOARD_CONNECTOR (CN2.9), LCD_CTP_FLEX_CONNECTORS (C13.2 R1.1)
I2C_SCL: MODULE_TO_MAIN_BOARD_CONNECTOR (CN2.5), LCD_CTP_FLEX_CONNECTORS (C14.2 J2.5)
I2C_SDA: MODULE_TO_MAIN_BOARD_CONNECTOR (CN2.3), LCD_CTP_FLEX_CONNECTORS (C11.2 J2.6)
LCD_B0: MODULE_TO_MAIN_BOARD_CONNECTOR (CN1.22), LCD_CTP_FLEX_CONNECTORS (U4.3)
LCD_B1: MODULE_TO_MAIN_BOARD_CONNECTOR (CN1.23), LCD_CTP_FLEX_CONNECTORS (U4.2)
LCD_B2: MODULE_TO_MAIN_BOARD_CONNECTOR (CN1.24), LCD_CTP_FLEX_CONNECTORS (U4.1)
LCD_B3: MODULE_TO_MAIN_BOARD_CONNECTOR (CN1.25), LCD_CTP_FLEX_CONNECTORS (U5.8)
LCD_B4: MODULE_TO_MAIN_BOARD_CONNECTOR (CN1.26), LCD_CTP_FLEX_CONNECTORS (U5.7)
LCD_B5: MODULE_TO_MAIN_BOARD_CONNECTOR (CN1.27), LCD_CTP_FLEX_CONNECTORS (U5.6)
LCD_B6: MODULE_TO_MAIN_BOARD_CONNECTOR (CN1.28), LCD_CTP_FLEX_CONNECTORS (U5.5)
LCD_B7: MODULE_TO_MAIN_BOARD_CONNECTOR (CN1.29), LCD_CTP_FLEX_CONNECTORS (U5.4)
LCD_BL_CTRL: MODULE_TO_MAIN_BOARD_CONNECTOR (CN1.39), LCD_CTP_FLEX_CONNECTORS (U1.2)
LCD_CLK: MODULE_TO_MAIN_BOARD_CONNECTOR (CN1.2), LCD_CTP_FLEX_CONNECTORS (C24.2 R3.1)
LCD_DE: MODULE_TO_MAIN_BOARD_CONNECTOR (CN1.33), LCD_CTP_FLEX_CONNECTORS (U5.1)
LCD_G0: MODULE_TO_MAIN_BOARD_CONNECTOR (CN1.13), LCD_CTP_FLEX_CONNECTORS (U3.3)
LCD_G1: MODULE_TO_MAIN_BOARD_CONNECTOR (CN1.14), LCD_CTP_FLEX_CONNECTORS (U3.2)
LCD_G2: MODULE_TO_MAIN_BOARD_CONNECTOR (CN1.15), LCD_CTP_FLEX_CONNECTORS (U3.1)
LCD_G3: MODULE_TO_MAIN_BOARD_CONNECTOR (CN1.16), LCD_CTP_FLEX_CONNECTORS (U4.8)
LCD_G4: MODULE_TO_MAIN_BOARD_CONNECTOR (CN1.17), LCD_CTP_FLEX_CONNECTORS (U4.7)
LCD_G5: MODULE_TO_MAIN_BOARD_CONNECTOR (CN1.18), LCD_CTP_FLEX_CONNECTORS (U4.6)
LCD_G6: MODULE_TO_MAIN_BOARD_CONNECTOR (CN1.19), LCD_CTP_FLEX_CONNECTORS (U4.5)
LCD_G7: MODULE_TO_MAIN_BOARD_CONNECTOR (CN1.20), LCD_CTP_FLEX_CONNECTORS (U4.4)
LCD_HSYNC: MODULE_TO_MAIN_BOARD_CONNECTOR (CN1.31), LCD_CTP_FLEX_CONNECTORS (U5.3)
LCD_R0: MODULE_TO_MAIN_BOARD_CONNECTOR (CN1.4), LCD_CTP_FLEX_CONNECTORS (U2.3)
LCD_R1: MODULE_TO_MAIN_BOARD_CONNECTOR (CN1.5), LCD_CTP_FLEX_CONNECTORS (U2.2)
LCD_R2: MODULE_TO_MAIN_BOARD_CONNECTOR (CN1.6), LCD_CTP_FLEX_CONNECTORS (U2.1)
LCD_R3: MODULE_TO_MAIN_BOARD_CONNECTOR (CN1.7), LCD_CTP_FLEX_CONNECTORS (U3.8)
LCD_R4: MODULE_TO_MAIN_BOARD_CONNECTOR (CN1.8), LCD_CTP_FLEX_CONNECTORS (U3.7)
LCD_R5: MODULE_TO_MAIN_BOARD_CONNECTOR (CN1.9), LCD_CTP_FLEX_CONNECTORS (U3.6)
LCD_R6: MODULE_TO_MAIN_BOARD_CONNECTOR (CN1.10), LCD_CTP_FLEX_CONNECTORS (U3.5)
LCD_R7: MODULE_TO_MAIN_BOARD_CONNECTOR (CN1.11), LCD_CTP_FLEX_CONNECTORS (U3.4)
LCD_RESET: MODULE_TO_MAIN_BOARD_CONNECTOR (CN1.34), LCD_CTP_FLEX_CONNECTORS (R6.1)
LCD_VSYNC: MODULE_TO_MAIN_BOARD_CONNECTOR (CN1.32), LCD_CTP_FLEX_CONNECTORS (U5.2)

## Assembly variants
LCD: not fitted C3 C10 C11 C13 C14 C24 C25 R6 R7 R10 R13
